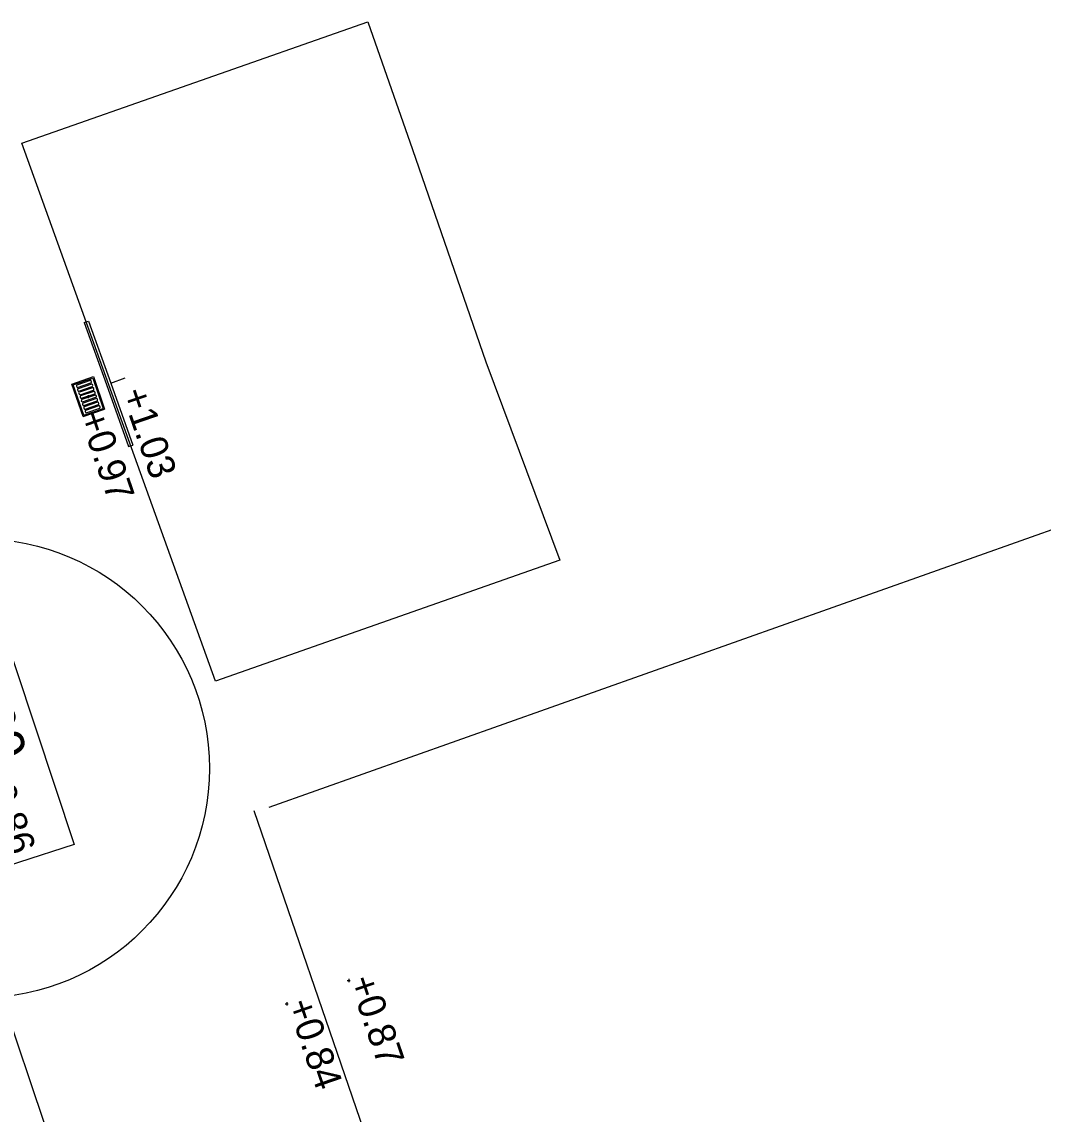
# Model space of a CAD drawing. Extents: x 122462 to 123306, y 485548 to 486417.
# Drawn here: x 122875.74 to 122889.09, y 486006.21 to 486020.49 of the extents above; entities that cross this region are included whole.
import ezdxf

# ---------------------------------------------------------------- set-up
doc = ezdxf.new("R2010")
doc.units = 0
for name, color, linetype in [('B-WE-GR-BOOM_BOOMDIAMETER-T25', 7, 'Continuous'), ('B-WE-OG-BEBOUWING_PORTIEK1-G', 7, 'Continuous'), ('B-WE-OG-HOOGTEPUNT-S', 7, 'Continuous'), ('B-WE-OG-TOPOKAART-G', 7, 'Continuous'), ('B-WE-RI-HWA_KOLK-S', 7, 'Continuous'), ('B-WE-VH-KANTOPSLUITING_ELEMENT_INRIT-G', 7, 'Continuous'), ('B-WE-VH-KANTOPSLUITING_OPSLUITBAND_100X200-G', 7, 'Continuous'), ('B-WE-VH-MATERIAALGRENS-G', 7, 'Continuous'), ('iba7-verkeersbord rood', 7, 'Continuous'), ('N werkgrens', 7, 'Continuous')]:
    doc.layers.add(name, color=color, linetype=linetype)

msp = doc.modelspace()

# ---------------------------------------------------------------- linework, layer by layer
at = {"layer": 'B-WE-OG-BEBOUWING_PORTIEK1-G'}
for p, q in [((122876.552, 486016.556), (122876.608, 486016.576)), ((122876.899, 486015.766), (122877.087, 486015.833)), ((122877.133, 486014.935), (122877.19, 486014.955))]:
    msp.add_line(p, q, dxfattribs=at)
for points in [[(122876.552, 486016.556), (122876.843, 486015.746), (122877.133, 486014.935)], [(122876.608, 486016.576), (122876.899, 486015.766), (122877.19, 486014.955)]]:
    msp.add_lwpolyline(points, dxfattribs=at)
at = {"layer": 'B-WE-OG-HOOGTEPUNT-S'}
for p, q in [((122876.586, 486015.589), (122876.626, 486015.589)), ((122876.606, 486015.609), (122876.606, 486015.569)), ((122880.012, 486007.973), (122880.012, 486007.933)), ((122879.992, 486007.953), (122880.032, 486007.953)), ((122879.181, 486007.648), (122879.221, 486007.648)), ((122879.201, 486007.668), (122879.201, 486007.628))]:
    msp.add_line(p, q, dxfattribs=at)
at = {"layer": 'B-WE-OG-TOPOKAART-G'}
msp.add_line((122878.269, 486011.868), (122875.739, 486018.903), dxfattribs=at)
msp.add_lwpolyline([(122875.739, 486018.903), (122880.26, 486020.49), (122880.846, 486018.821), (122881.803, 486016.043), (122882.774, 486013.448), (122878.269, 486011.868)], dxfattribs=at)
at = {"layer": 'B-WE-RI-HWA_KOLK-S'}
for p, q in [((122876.391, 486015.753), (122876.675, 486015.85)), ((122876.41, 486015.743), (122876.665, 486015.831)), ((122876.665, 486015.831), (122876.801, 486015.434)), ((122876.675, 486015.85), (122876.82, 486015.424)), ((122876.537, 486015.327), (122876.391, 486015.753)), ((122876.546, 486015.346), (122876.41, 486015.743)), ((122876.537, 486015.327), (122876.82, 486015.424)), ((122876.546, 486015.346), (122876.801, 486015.434))]:
    msp.add_line(p, q, dxfattribs=at)
for points in [[(122876.45, 486015.727), (122876.454, 486015.715)], [(122876.631, 486015.799), (122876.457, 486015.739)], [(122876.467, 486015.709), (122876.641, 486015.769)], [(122876.467, 486015.679), (122876.47, 486015.668)], [(122876.647, 486015.752), (122876.473, 486015.692)], [(122876.483, 486015.662), (122876.657, 486015.721)], [(122876.663, 486015.704), (122876.489, 486015.645)], [(122876.647, 486015.782), (122876.644, 486015.793)], [(122876.664, 486015.734), (122876.66, 486015.746)], [(122876.68, 486015.687), (122876.676, 486015.698)], [(122876.483, 486015.632), (122876.487, 486015.621)], [(122876.499, 486015.614), (122876.674, 486015.674)], [(122876.499, 486015.585), (122876.503, 486015.573)], [(122876.68, 486015.657), (122876.505, 486015.597)], [(122876.515, 486015.537), (122876.519, 486015.526)], [(122876.516, 486015.567), (122876.69, 486015.627)], [(122876.696, 486015.61), (122876.521, 486015.55)], [(122876.532, 486015.52), (122876.706, 486015.58)], [(122876.712, 486015.563), (122876.538, 486015.503)], [(122876.696, 486015.64), (122876.692, 486015.651)], [(122876.712, 486015.592), (122876.708, 486015.604)], [(122876.728, 486015.545), (122876.725, 486015.556)], [(122876.531, 486015.49), (122876.535, 486015.479)], [(122876.548, 486015.473), (122876.722, 486015.532)], [(122876.548, 486015.443), (122876.551, 486015.431)], [(122876.728, 486015.515), (122876.554, 486015.456)], [(122876.564, 486015.425), (122876.738, 486015.485)], [(122876.564, 486015.396), (122876.568, 486015.384)], [(122876.744, 486015.468), (122876.57, 486015.408)], [(122876.58, 486015.378), (122876.755, 486015.438)], [(122876.745, 486015.498), (122876.741, 486015.509)], [(122876.761, 486015.45), (122876.757, 486015.462)]]:
    msp.add_lwpolyline(points, dxfattribs=at)
for centre, start, end in [((122876.46, 486015.73), 108.9043, 198.9043), ((122876.464, 486015.719), 198.9043, 288.9043), ((122876.476, 486015.683), 108.9043, 198.9043), ((122876.634, 486015.79), 18.9043, 108.9043), ((122876.638, 486015.778), 288.9043, 18.9043), ((122876.65, 486015.742), 18.9043, 108.9043), ((122876.654, 486015.731), 288.9043, 18.9043), ((122876.667, 486015.695), 18.9043, 108.9043), ((122876.67, 486015.684), 288.9043, 18.9043), ((122876.48, 486015.671), 198.9043, 288.9043), ((122876.492, 486015.635), 108.9043, 198.9043), ((122876.496, 486015.624), 198.9043, 288.9043), ((122876.508, 486015.588), 108.9043, 198.9043), ((122876.512, 486015.577), 198.9043, 288.9043), ((122876.525, 486015.541), 108.9043, 198.9043), ((122876.683, 486015.648), 18.9043, 108.9043), ((122876.687, 486015.636), 288.9043, 18.9043), ((122876.699, 486015.6), 18.9043, 108.9043), ((122876.703, 486015.589), 288.9043, 18.9043), ((122876.715, 486015.553), 18.9043, 108.9043), ((122876.719, 486015.542), 288.9043, 18.9043), ((122876.529, 486015.529), 198.9043, 288.9043), ((122876.541, 486015.493), 108.9043, 198.9043), ((122876.545, 486015.482), 198.9043, 288.9043), ((122876.557, 486015.446), 108.9043, 198.9043), ((122876.561, 486015.435), 198.9043, 288.9043), ((122876.573, 486015.399), 108.9043, 198.9043), ((122876.731, 486015.506), 18.9043, 108.9043), ((122876.735, 486015.494), 288.9043, 18.9043), ((122876.748, 486015.458), 18.9043, 108.9043), ((122876.751, 486015.447), 288.9043, 18.9043), ((122876.577, 486015.387), 198.9043, 288.9043)]:
    msp.add_arc(centre, 0.01, start, end, dxfattribs=at)
at = {"layer": 'B-WE-VH-KANTOPSLUITING_ELEMENT_INRIT-G'}
msp.add_lwpolyline([(122876.1, 486004.342), (122876.567, 486004.501), (122874.962, 486009.263), (122874.461, 486009.099)], close=True, dxfattribs=at)
at = {"layer": 'B-WE-VH-KANTOPSLUITING_OPSLUITBAND_100X200-G'}
msp.add_lwpolyline([(122875.003, 486012.672), (122875.403, 486012.797), (122876.421, 486009.733), (122874.962, 486009.263)], dxfattribs=at)
at = {"layer": 'B-WE-VH-MATERIAALGRENS-G'}
msp.add_lwpolyline([(122878.772, 486010.178), (122880.204, 486006.001), (122880.488, 486005.883)], dxfattribs=at)
at = {"layer": 'iba7-verkeersbord rood'}
msp.add_circle((122875.191, 486010.727), 3, dxfattribs=at)
at = {"layer": 'N werkgrens'}
msp.add_line((122889.546, 486013.97), (122878.968, 486010.214), dxfattribs=at)

# ---------------------------------------------------------------- texts
at = {"layer": 'B-WE-GR-BOOM_BOOMDIAMETER-T25'}
msp.add_text('60', height=0.5, rotation=289.2634, dxfattribs=at).set_placement((122875.102, 486011.471))
at = {"layer": 'B-WE-OG-HOOGTEPUNT-S'}
for s, p in [('+1.03', (122877.035, 486015.638)), ('+0.97', (122876.483, 486015.337)), ('+0.86', (122875.193, 486010.724)), ('+0.87', (122880.012, 486007.953)), ('+0.84', (122879.201, 486007.648))]:
    msp.add_text(s, height=0.36, rotation=289, dxfattribs=at).set_placement(p)

doc.saveas('drawing.dxf')
